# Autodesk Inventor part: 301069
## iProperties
Created: 2007-12
Part Number: 301069
Document SubType Name: Modeling
Designer: TH
Density: 7.85 g/cm^3
Mass: 284.933 g
Surface Area: 485.8 cm^2
Volume: 36.2972 cm^3
Material: Steel
Description: PIVOT BAR
Component Category: Back Component
Author: TH
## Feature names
1. Extrusion1
